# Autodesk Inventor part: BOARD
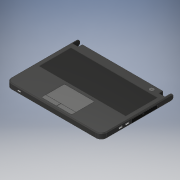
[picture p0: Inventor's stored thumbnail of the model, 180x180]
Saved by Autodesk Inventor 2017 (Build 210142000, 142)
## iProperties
Created: 2017-02
Part Number: BOARD
Material: Generic
Document SubType Name: Modeling
Designer: Ali
Density: 1 g/cm^3
Appearance: Default
Author: Ali
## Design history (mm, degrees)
sketch "Sketch1"
  geometry: L1 (-165, -250)-(-165, -20); L2 (-145, 0)-(145, 0); L3 (165, -20)-(165, -250); L4 (-139.5, -228)-(-160.5, -228); L5 (-160.5, -228)-(-160.5, -250); L6 (-160.5, -250)-(-165, -250); L7 (-139.5, -228)-(-139.5, -239); L8 (-139.5, -239)-(139.5, -239); L9 (139.5, -239)-(139.5, -228); L10 (139.5, -228)-(160.5, -228); L11 (160.5, -228)-(160.5, -250); L12 (160.5, -250)-(165, -250); A1 r 20 centre (145, -20) between (165, -20) and (145, 0); A2 r 20 centre (-145, -20) between (-145, 0) and (-165, -20); 2 further points
  constraints: 24 end point, 4 point on circle, 4 point on line, 4 tangent, 2 centre point, 1 equal radius, 1 parallel
  dimensions: "d19" = 279 distance of L7.end L8.end; "d20" = 11 distance of L4.start L7.end; "d21" = 21 distance of L4.end L4.start; "d22" = 22 distance of L5.end L4.end
extrude "BOARD" new body sketch "Sketch1" distance "d23" = 20; taper "d24" = 0 deg
chamfer "HINGE CHAMFER" distance "d25" = 2.5; stored, may be unused: second distance "d26" = 1.25, angle "d27" = 45 deg
sketch "Sketch2"
  geometry: L1 (-47.5, 10)-(47.5, 10); L2 (52.5, 15)-(52.5, 85); L3 (47.5, 90)-(-47.5, 90); L4 (-52.5, 85)-(-52.5, 15); A1 r 5 centre (-47.5, 85) between (-47.5, 90) and (-52.5, 85); A2 r 5 centre (47.5, 85) between (52.5, 85) and (47.5, 90); A3 r 5 centre (47.5, 15) between (47.5, 10) and (52.5, 15); A4 r 5 centre (-47.5, 15) between (-52.5, 15) and (-47.5, 10); 3 further points
  constraints: 8 end point, 8 point on circle, 8 tangent, 6 point on line, 4 centre point, 3 equal radius, 2 parallel, 1 horizontal, 1 perpendicular
  dimensions: "d32" = 105 distance of point (-52.5, 90) point (52.5, 90); "d33" = 80 distance of point (52.5, 90) point (52.5, 10); "d34" = 5 radius of A1 (derived)
extrude "TOUCH PAD" cut sketch "Sketch2" distance "d35" = 0.5; taper "d36" = 0 deg
sketch "Sketch3"
  geometry: L1 (-52.5, 25)-(-0.5, 25); L2 (-0.5, 25)-(-0.5, 10); L3 (-0.5, 10)-(-47.5, 10); L4 (-52.5, 15)-(-52.5, 25); A1 r 5 centre (-47.5, 15) between (-52.5, 15) and (-47.5, 10); 1 further point
  constraints: 8 end point, 2 parallel, 2 point on circle, 2 point on line, 2 tangent, 1 centre point, 1 horizontal, 1 perpendicular
  dimensions: "d39" = 52 distance of L2.end point (-52.5, 10); "d40" = 15 distance of L1.end L2.end; "d41" = 5 radius of A1 (derived)
extrude "LEFT BUTTON" join sketch "Sketch3" distance "d42" = 0.6; taper "d43" = 0 deg
sketch "Sketch4"
  geometry: L1 (0.5, 25)-(52.5, 25); L2 (52.5, 25)-(52.5, 15); L3 (47.5, 10)-(0.5, 10); L4 (0.5, 10)-(0.5, 25); A1 r 5 centre (47.5, 15) between (47.5, 10) and (52.5, 15)
  constraints: 8 end point, 2 parallel, 2 point on circle, 2 tangent, 1 centre point, 1 horizontal, 1 perpendicular
extrude "RIGHT BUTTON" join sketch "Sketch4" distance "d48" = 0.6; taper "d49" = 0 deg
sketch "Sketch5"
  geometry: L1 (-150, 210)-(150, 210); L2 (150, 210)-(150, 100); L3 (150, 100)-(-150, 100); L4 (-150, 100)-(-150, 210)
  constraints: 8 end point, 2 parallel, 1 horizontal, 1 perpendicular
  dimensions: "d57" = 300 distance of L2.end L3.end; "d58" = 110 distance of L1.end L2.end
extrude "KEYBOARD BASE" cut sketch "Sketch5" distance "d59" = 0.3; taper "d60" = 0 deg
chamfer "KEYBOARD CHAMFER" distance "d61" = 0.3; stored, may be unused: second distance "d62" = 1.25, angle "d63" = 45 deg
sketch "Sketch6"
  geometry: L1 (230, 20)-(222.003, 20); L2 (222.003, 20)-(222.003, 0); L3 (222.003, 0)-(230, 0); L4 (230, 0)-(230, 20); 1 further point
  constraints: 8 end point, 2 parallel, 1 horizontal, 1 perpendicular
extrude "CUT" cut sketch "Sketch6" distance "d64" = 330; taper "d65" = 0 deg
sketch "Sketch7"
  geometry: L1 (222.003, 20)-(222.003, 0); A1 r 10 centre (222.003, 10) between (222.003, 0) and (222.003, 20); 1 further point
  constraints: 2 end point, 2 point on circle, 1 centre point
extrude "ROUND BASE" join sketch "Sketch7" distance "d66" = 4.5; taper "d67" = 0 deg
sketch "Sketch8"
  geometry: L1 (-222.003, 20)-(-222.003, 0); A1 r 10 centre (-222.003, 10) between (-222.003, 20) and (-222.003, 0); 1 further point
  constraints: 2 end point, 2 point on circle, 1 centre point
extrude "ROUND BASE 1" join sketch "Sketch8" distance "d68" = 4.5; taper "d69" = 0 deg
chamfer "BOARD BASE" distance "d70" = 2.5; stored, may be unused: second distance "d71" = 1.25, angle "d72" = 45 deg
sketch "Sketch9"
  geometry: C1 r 7.5 at (115, 225); 1 further point
  constraints: 1 centre point
  dimensions: "d73" = 15 diameter of C1
extrude "POWER BUTTON" cut sketch "Sketch9" distance "d74" = 0.05; taper "d75" = 0 deg
sketch "Sketch10"
  geometry: 2 further points
hole "POWER BUTTON 1" sketch "Sketch10" at (0, 0) diameter "d76" = 2; stored, may be unused: countersink angle "d80" = 90 deg, drill point angle "d82" = 118 deg; dims "d77" = 7.5, "d78" = 3.75, "d79" = 2.5, "d81" = 0.05
sketch "Sketch11"
  geometry: 2 further points
hole "CHARGING PORT" sketch "Sketch11" at (25, 0) diameter "d85" = 6.5; stored, may be unused: countersink angle "d89" = 90 deg, drill point angle "d91" = 0 deg; dims "d86" = 7.5, "d87" = 8.5, "d88" = 0.1, "d90" = 5
sketch "Sketch12"
  geometry: L1 (56.5, 4)-(56.5, -4); L2 (55, 4)-(55, -4); A1 r 0.75 centre (55.75, 4) between (56.5, 4) and (55, 4); A2 r 0.75 centre (55.75, -4) between (55, -4) and (56.5, -4); 1 further point
  constraints: 4 end point, 4 point on circle, 2 centre point
extrude "HEAT SINK" cut sketch "Sketch12" distance "d97" = 2; taper "d98" = 0 deg
pattern_linear "HEAT SINK PATTERN" dims "d101" = 4
sketch "Sketch13"
  geometry: L1 (120, 3)-(133, 3); L2 (133, -3)-(131.362, -4.147); L3 (133, 3)-(133, -3); L4 (120, 3)-(120, -3); L5 (120, -3)-(121.638, -4.147); L6 (121.638, -4.147)-(131.362, -4.147)
  constraints: 12 end point
extrude "HDMI PORT" cut sketch "Sketch13" distance "d111" = 5; taper "d112" = 0 deg
sketch "Sketch14"
  geometry: L1 (120.305, -1)-(132.705, -1); L2 (132.705, -1)-(132.705, -1.5); L3 (132.705, -1.5)-(120.305, -1.5); L4 (120.305, -1.5)-(120.305, -1); 1 further point
  constraints: 8 end point, 2 parallel, 1 horizontal, 1 perpendicular
extrude "HDMI SLOT" join sketch "Sketch14" distance "d115" = 5; taper "d116" = 0 deg
sketch "Sketch15"
  geometry: L1 (158, -3)-(145, -3); L2 (145, -3)-(145, 3); L3 (145, 3)-(158, 3); L4 (158, 3)-(158, -3)
  constraints: 8 end point, 2 parallel, 1 horizontal, 1 perpendicular
extrude "USB PORT" cut sketch "Sketch15" distance "d121" = 5; taper "d122" = 0 deg
sketch "Sketch16"
  geometry: L1 (145.3, 1.5)-(157.7, 1.5); L2 (157.7, 1.5)-(157.7, 1); L3 (157.7, 1)-(145.3, 1); L4 (145.3, 1)-(145.3, 1.5); 1 further point
  constraints: 8 end point, 2 parallel, 1 horizontal, 1 perpendicular
  dimensions: "d126" = 12.4 distance of L2.end L3.end; "d127" = 0.5 distance of L1.end L2.end
extrude "USB SLOT" join sketch "Sketch16" distance "d128" = 5; taper "d129" = 0 deg
sketch "Sketch17"
  geometry: L1 (207.5, -2.5)-(172.5, -2.5); L2 (170, 0)-(170, 0); L3 (172.5, 2.5)-(207.5, 2.5); L4 (210, 0)-(210, 0); A1 r 2.5 centre (207.5, 0) between (210, 0) and (207.5, 2.5); A2 r 2.5 centre (207.5, 0) between (207.5, -2.5) and (210, 0); A3 r 2.5 centre (172.5, 0) between (172.5, 2.5) and (170, 0); A4 r 2.5 centre (172.5, 0) between (170, 0) and (172.5, -2.5); 3 further points
  constraints: 8 end point, 8 point on circle, 8 tangent, 6 point on line, 4 centre point, 3 equal radius, 2 parallel, 1 horizontal, 1 perpendicular
  dimensions: "d134" = 40 distance of point (170, 2.5) point (210, 2.5); "d136" = 5 distance of point (210, 2.5) point (210, -2.5); "d137" = 2.5 radius of A1
extrude "MEMORY SLOT" cut sketch "Sketch17" distance "d138" = 5; taper "d139" = 0 deg
sketch "Sketch18"
  geometry: L1 (-132.5, 5.1)-(-52.5, 5.1); L2 (-47.5, 0.1)-(-47.5, -7.4); L3 (-47.5, -7.4)-(-137.5, -7.4); L4 (-137.5, -7.4)-(-137.5, 0.1); A1 r 5 centre (-132.5, 0.1) between (-132.5, 5.1) and (-137.5, 0.1); A2 r 5 centre (-52.5, 0.1) between (-47.5, 0.1) and (-52.5, 5.1); 1 further point
  constraints: 8 end point, 4 point on circle, 4 tangent, 2 centre point, 2 parallel, 2 point on line, 1 horizontal, 1 perpendicular
  dimensions: "d147" = 5 radius of A1; "d148" = 12.5 distance of point (-47.5, 5.1) L2.end; "d150" = 90 distance of L2.end L3.end
extrude "DISK HOLDER" join sketch "Sketch18" distance "d151" = 0.2; taper "d152" = 0 deg
sketch "Sketch19"
  geometry: L1 (-94, 1.6)-(-98, 1.6); L2 (-98.5, 1.1)-(-98.5, 0.6); L3 (-98, 0.1)-(-94, 0.1); L4 (-93.5, 0.6)-(-93.5, 1.1); A1 r 0.5 centre (-98, 1.1) between (-98, 1.6) and (-98.5, 1.1); A2 r 0.5 centre (-98, 0.6) between (-98.5, 0.6) and (-98, 0.1); A3 r 0.5 centre (-94, 0.6) between (-94, 0.1) and (-93.5, 0.6); A4 r 0.5 centre (-94, 1.1) between (-93.5, 1.1) and (-94, 1.6); 4 further points
  constraints: 8 end point, 8 point on circle, 8 tangent, 6 point on line, 4 centre point, 3 equal radius, 2 parallel, 1 horizontal, 1 perpendicular
  dimensions: "d158" = 5 distance of point (-93.5, 1.6) point (-98.5, 1.6); "d159" = 1.5 distance of point (-93.5, 0.1) point (-93.5, 1.6); "d160" = 0.5 radius of A1 (derived)
extrude "DISK HOLDER BUTTON" join sketch "Sketch19" distance "d161" = 0.05; taper "d162" = 0 deg
sketch "Sketch22"
  geometry: L1 (158, -3)-(145, -3); L2 (145, -3)-(145, 3); L3 (145, 3)-(158, 3); L4 (158, 3)-(158, -3)
  constraints: 8 end point, 2 parallel, 1 horizontal, 1 perpendicular
extrude "USB PORT 1" cut sketch "Sketch22" taper "d172" = 0 deg; distance "d173" = 5
sketch "Sketch23"
  geometry: L1 (145.3, 1.5)-(157.7, 1.5); L2 (157.7, 1.5)-(157.7, 1); L3 (157.7, 1)-(145.3, 1); L4 (145.3, 1)-(145.3, 1.5); 1 further point
  constraints: 8 end point, 2 parallel, 1 horizontal, 1 perpendicular
  dimensions: "d174" = 12.4 distance of L2.end L3.end; "d175" = 0.5 distance of L1.end L2.end
extrude "USB SLOT 1" join sketch "Sketch23" taper "d177" = 0 deg; distance "d178" = 5
sketch "Sketch24"
  geometry: L1 (158, -3)-(145, -3); L2 (145, -3)-(145, 3); L3 (145, 3)-(158, 3); L4 (158, 3)-(158, -3)
  constraints: 8 end point, 2 parallel, 1 horizontal, 1 perpendicular
extrude "USB PORT 2" cut sketch "Sketch24" taper "d180" = 0 deg; distance "d181" = 5
sketch "Sketch25"
  geometry: L1 (145.3, 1.5)-(157.7, 1.5); L2 (157.7, 1.5)-(157.7, 1); L3 (157.7, 1)-(145.3, 1); L4 (145.3, 1)-(145.3, 1.5); 1 further point
  constraints: 8 end point, 2 parallel, 1 horizontal, 1 perpendicular
  dimensions: "d182" = 12.4 distance of L2.end L3.end; "d183" = 0.5 distance of L1.end L2.end
extrude "USB SLOT 2" join sketch "Sketch25" taper "d185" = 0 deg; distance "d186" = 5
sketch "Sketch26"
  geometry: L1 (22, -5.5)-(30, -5.5); L2 (32, -7.5)-(32, -7.5); L3 (30, -9.5)-(22, -9.5); L4 (20, -7.5)-(20, -7.5); A1 r 2 centre (22, -7.5) between (22, -5.5) and (20, -7.5); A2 r 2 centre (22, -7.5) between (20, -7.5) and (22, -9.5); A3 r 2 centre (30, -7.5) between (30, -9.5) and (32, -7.5); A4 r 2 centre (30, -7.5) between (32, -7.5) and (30, -5.5); 4 further points
  constraints: 8 end point, 8 point on circle, 8 tangent, 6 point on line, 4 centre point, 3 equal radius, 2 parallel, 1 horizontal, 1 perpendicular
  dimensions: "d190" = 12 distance of point (32, -9.5) point (20, -9.5); "d191" = 4 distance of point (32, -5.5) point (32, -9.5); "d192" = 2 radius of A1 (derived)
extrude "BATTERY INDICATOR" join sketch "Sketch26" distance "d193" = 0.05; taper "d194" = 0 deg
body "Solid1"
